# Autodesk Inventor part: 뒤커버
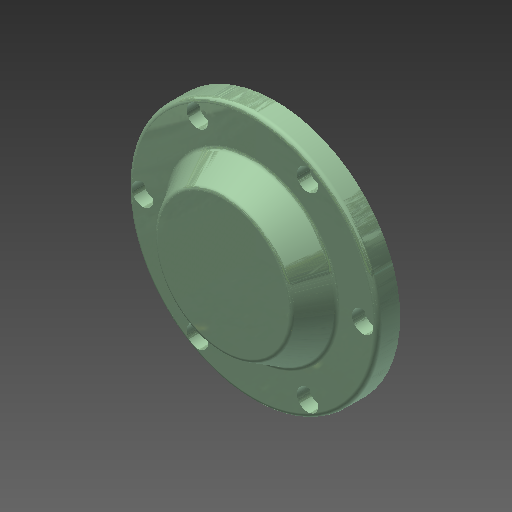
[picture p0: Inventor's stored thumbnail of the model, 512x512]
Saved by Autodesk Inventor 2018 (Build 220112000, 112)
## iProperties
Created: 2013-01
Part Number: 뒤커버
Document SubType Name: Modeling
Designer: 한국산업디자인학원[gmhk.co.kr]
Density: 2.71 g/cm^3
Material: 알루미늄 6061
Mass: 415.969 g
Surface Area: 272.105 cm^2
Volume: 153.494 cm^3
Appearance: 알루미늄 - 평지(1)
Author: 한국산업디자인학원[gmhk.co.kr]
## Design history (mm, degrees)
sketch "스케치2"
  geometry: L1 (-55, 0)-(55, 0) reference; L2 (35.98, -6)-(-35.98, -6) reference; L3 (-42.5, -25)-(-42.5, 0) reference; L4 (-37, -6)-(-37, 0); L5 (-55, 0)-(-55, 10); L6 (-55, 10)-(-37.5, 10); L7 (-37, -6)-(-42.5, -6); L8 (-37.5, 10)-(-29.994, 23); L9 (-29.994, 23)-(0, 23); L10 (-55, 0)-(-42.5, 0); L11 (-42.5, -6)-(-42.5, 0); L12 (0, 0)-(0, 23); L13 (0, 0)-(-37, 0)
  constraints: 22 end point, 4 perpendicular, 3 collinear, 2 parallel, 2 point on line, 1 vertical, 2 other
  dimensions: "d2" = 10 distance of L1.start L5.end; "d4" = 120 deg angle of L8 L6; "d5" = 13 distance between parallel lines of L6 L9; "d6" = 74 diameter of L4 L12; "d7" = 75 diameter of L6.end L12
revolve "회전1" sketch "스케치2" stored, may be unused: angle "d8" = 90 deg
fillet "모깎기1" dims "d9" = 2
sketch "스케치3"
  geometry: C1 r 2.067 at (48.5, 0) reference; 1 further point
hole "구멍1" sketch "스케치3" at (48.5, 0) diameter "d10" = 5.5; stored, may be unused: countersink angle "d14" = 90 deg, drill point angle "d16" = 118 deg; dims "d11" = 6, "d12" = 9.5, "d13" = 5.4, "d15" = 8
fillet "모깎기2" dims "d20" = 3
chamfer "모따기1" distance "d21" = 1; stored, may be unused: second distance "d22" = 2, angle "d23" = 45 deg
node "솔리드1"
pattern_circular "원형 패턴1" dims angle "d18" = 360 deg
node "참조1"
node "참조2"
node "참조3"
